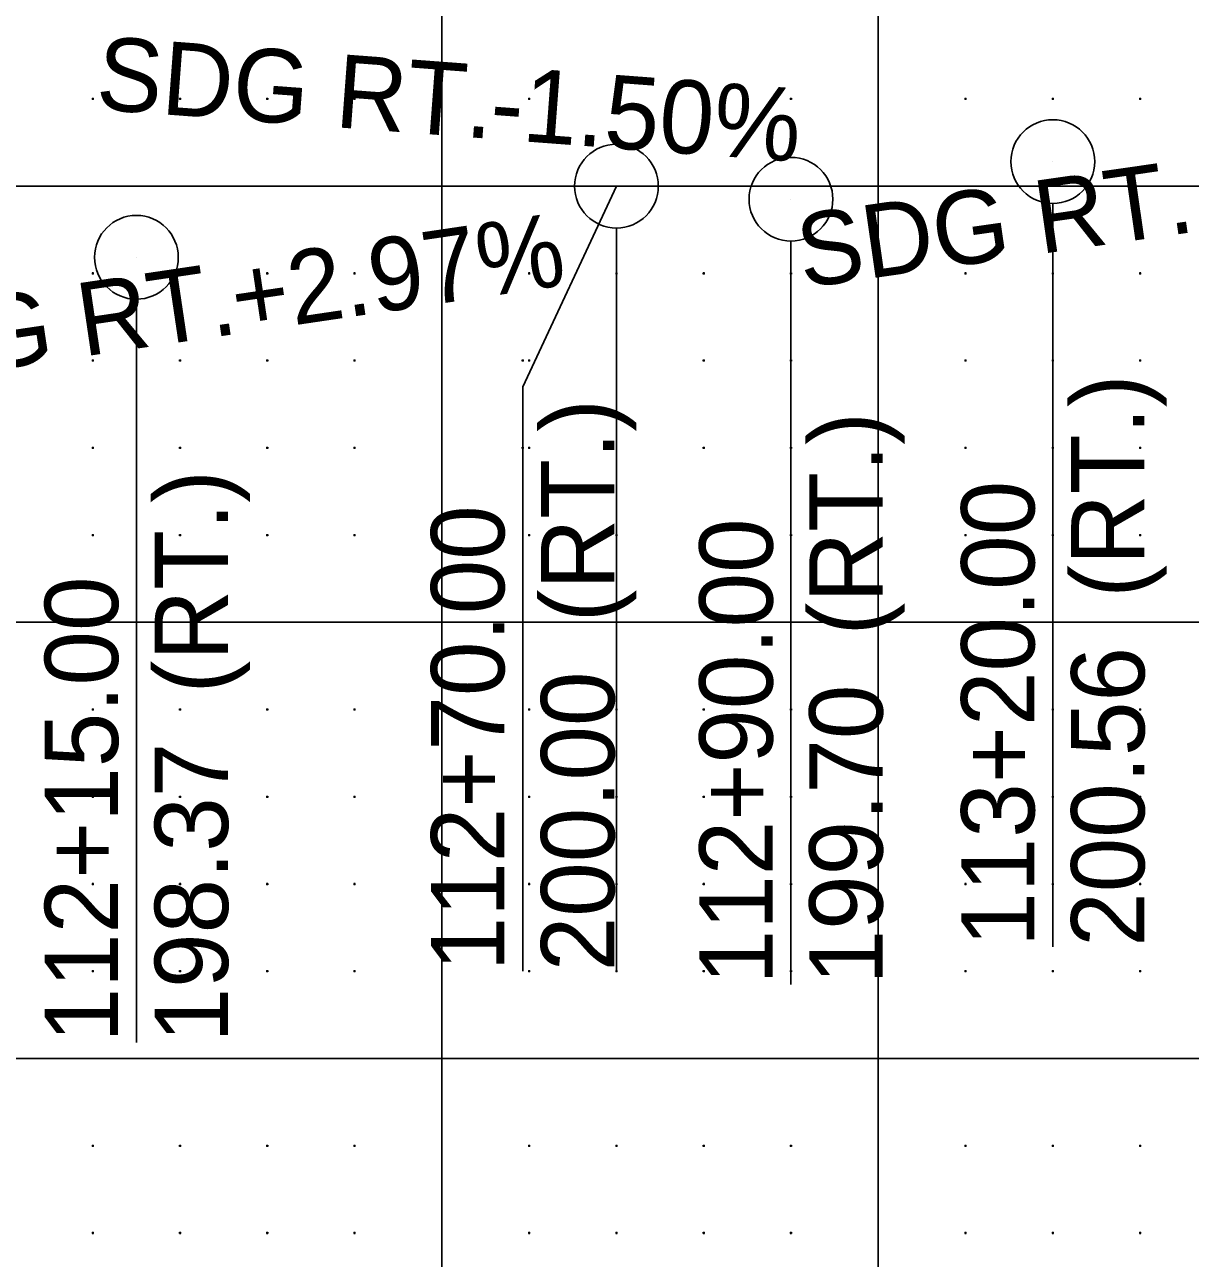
# Model space of a CAD drawing. Extents: x 471 to 2121, y 140 to 650.
# Drawn here: x 1838.3 to 1971.8, y 277.1 to 418.5 of the extents above; entities that cross this region are included whole.
import ezdxf

# ---------------------------------------------------------------- set-up
doc = ezdxf.new("R2010")
doc.units = 0
doc.layers.add('DSN_DRFT_Border Grid', color=7, linetype='Continuous')
doc.layers.add('Triangles', color=7, linetype='Continuous')

msp = doc.modelspace()

# ---------------------------------------------------------------- linework, layer by layer
at = {"layer": 'DSN_DRFT_Border Grid'}
for p, q in [((1886.06, 150), (1886.06, 650)), ((1886.06, 150), (1886.06, 650)), ((1936.06, 150), (1936.06, 650)), ((1936.06, 150), (1936.06, 650)), ((1846.06, 410.12), (1846.06, 409.88)), ((1846.06, 410.12), (1846.06, 409.88)), ((1856.06, 410.12), (1856.06, 409.88)), ((1856.06, 410.12), (1856.06, 409.88)), ((1866.06, 410.12), (1866.06, 409.88)), ((1866.06, 410.12), (1866.06, 409.88)), ((1876.06, 410.12), (1876.06, 409.88)), ((1876.06, 410.12), (1876.06, 409.88)), ((1896.06, 410.12), (1896.06, 409.88)), ((1896.06, 410.12), (1896.06, 409.88)), ((1906.06, 410.12), (1906.06, 409.88)), ((1906.06, 410.12), (1906.06, 409.88)), ((1916.06, 410.12), (1916.06, 409.88)), ((1916.06, 410.12), (1916.06, 409.88)), ((1926.06, 410.12), (1926.06, 409.88)), ((1926.06, 410.12), (1926.06, 409.88)), ((1946.06, 410.12), (1946.06, 409.88)), ((1946.06, 410.12), (1946.06, 409.88)), ((1956.06, 410.12), (1956.06, 409.88)), ((1956.06, 410.12), (1956.06, 409.88)), ((1966.06, 410.12), (1966.06, 409.88)), ((1966.06, 410.12), (1966.06, 409.88)), ((1846.18, 410), (1845.94, 410)), ((1846.18, 410), (1845.94, 410)), ((1856.18, 410), (1855.94, 410)), ((1856.18, 410), (1855.94, 410)), ((1866.18, 410), (1865.94, 410)), ((1866.18, 410), (1865.94, 410)), ((1876.18, 410), (1875.94, 410)), ((1876.18, 410), (1875.94, 410)), ((1896.18, 410), (1895.94, 410)), ((1896.18, 410), (1895.94, 410)), ((1906.18, 410), (1905.94, 410)), ((1906.18, 410), (1905.94, 410)), ((1916.18, 410), (1915.94, 410)), ((1916.18, 410), (1915.94, 410)), ((1926.18, 410), (1925.94, 410)), ((1926.18, 410), (1925.94, 410)), ((1946.18, 410), (1945.94, 410)), ((1946.18, 410), (1945.94, 410)), ((1956.18, 410), (1955.94, 410)), ((1956.18, 410), (1955.94, 410)), ((1966.18, 410), (1965.94, 410)), ((1966.18, 410), (1965.94, 410)), ((521.06, 400), (2071.06, 400)), ((521.06, 400), (2071.06, 400)), ((1846.18, 390), (1845.94, 390)), ((1846.18, 390), (1845.94, 390)), ((1846.06, 390.12), (1846.06, 389.88)), ((1846.06, 390.12), (1846.06, 389.88)), ((1856.18, 390), (1855.94, 390)), ((1856.18, 390), (1855.94, 390)), ((1856.06, 390.12), (1856.06, 389.88)), ((1856.06, 390.12), (1856.06, 389.88)), ((1866.18, 390), (1865.94, 390)), ((1866.18, 390), (1865.94, 390)), ((1866.06, 390.12), (1866.06, 389.88)), ((1866.06, 390.12), (1866.06, 389.88)), ((1876.18, 390), (1875.94, 390)), ((1876.18, 390), (1875.94, 390)), ((1876.06, 390.12), (1876.06, 389.88)), ((1876.06, 390.12), (1876.06, 389.88)), ((1896.18, 390), (1895.94, 390)), ((1896.18, 390), (1895.94, 390)), ((1896.06, 390.12), (1896.06, 389.88)), ((1896.06, 390.12), (1896.06, 389.88)), ((1906.18, 390), (1905.94, 390)), ((1906.18, 390), (1905.94, 390)), ((1906.06, 390.12), (1906.06, 389.88)), ((1906.06, 390.12), (1906.06, 389.88)), ((1916.18, 390), (1915.94, 390)), ((1916.18, 390), (1915.94, 390)), ((1916.06, 390.12), (1916.06, 389.88)), ((1916.06, 390.12), (1916.06, 389.88)), ((1926.18, 390), (1925.94, 390)), ((1926.18, 390), (1925.94, 390)), ((1926.06, 390.12), (1926.06, 389.88)), ((1926.06, 390.12), (1926.06, 389.88)), ((1946.18, 390), (1945.94, 390)), ((1946.18, 390), (1945.94, 390)), ((1946.06, 390.12), (1946.06, 389.88)), ((1946.06, 390.12), (1946.06, 389.88)), ((1956.18, 390), (1955.94, 390)), ((1956.18, 390), (1955.94, 390)), ((1956.06, 390.12), (1956.06, 389.88)), ((1956.06, 390.12), (1956.06, 389.88)), ((1966.18, 390), (1965.94, 390)), ((1966.18, 390), (1965.94, 390)), ((1966.06, 390.12), (1966.06, 389.88)), ((1966.06, 390.12), (1966.06, 389.88)), ((1846.18, 380), (1845.94, 380)), ((1846.18, 380), (1845.94, 380)), ((1846.06, 380.12), (1846.06, 379.88)), ((1846.06, 380.12), (1846.06, 379.88)), ((1856.18, 380), (1855.94, 380)), ((1856.18, 380), (1855.94, 380)), ((1856.06, 380.12), (1856.06, 379.88)), ((1856.06, 380.12), (1856.06, 379.88)), ((1866.18, 380), (1865.94, 380)), ((1866.18, 380), (1865.94, 380)), ((1866.06, 380.12), (1866.06, 379.88)), ((1866.06, 380.12), (1866.06, 379.88)), ((1876.18, 380), (1875.94, 380)), ((1876.18, 380), (1875.94, 380)), ((1876.06, 380.12), (1876.06, 379.88)), ((1876.06, 380.12), (1876.06, 379.88)), ((1895.44, 380), (1895.2, 380)), ((1895.44, 380), (1895.2, 380)), ((1895.32, 380.12), (1895.32, 379.88)), ((1895.32, 380.12), (1895.32, 379.88)), ((1896.18, 380), (1895.94, 380)), ((1896.18, 380), (1895.94, 380)), ((1896.06, 380.12), (1896.06, 379.88)), ((1896.06, 380.12), (1896.06, 379.88)), ((1916.18, 380), (1915.94, 380)), ((1916.18, 380), (1915.94, 380)), ((1916.06, 380.12), (1916.06, 379.88)), ((1916.06, 380.12), (1916.06, 379.88)), ((1926.18, 380), (1925.94, 380)), ((1926.18, 380), (1925.94, 380)), ((1926.06, 380.12), (1926.06, 379.88)), ((1926.06, 380.12), (1926.06, 379.88)), ((1946.18, 380), (1945.94, 380)), ((1946.18, 380), (1945.94, 380)), ((1946.06, 380.12), (1946.06, 379.88)), ((1946.06, 380.12), (1946.06, 379.88)), ((1956.18, 380), (1955.94, 380)), ((1956.18, 380), (1955.94, 380)), ((1956.06, 380.12), (1956.06, 379.88)), ((1956.06, 380.12), (1956.06, 379.88)), ((1966.18, 380), (1965.94, 380)), ((1966.18, 380), (1965.94, 380)), ((1966.06, 380.12), (1966.06, 379.88)), ((1966.06, 380.12), (1966.06, 379.88)), ((1846.18, 370), (1845.94, 370)), ((1846.18, 370), (1845.94, 370)), ((1846.06, 370.12), (1846.06, 369.88)), ((1846.06, 370.12), (1846.06, 369.88)), ((1856.18, 370), (1855.94, 370)), ((1856.18, 370), (1855.94, 370)), ((1856.06, 370.12), (1856.06, 369.88)), ((1856.06, 370.12), (1856.06, 369.88)), ((1866.18, 370), (1865.94, 370)), ((1866.18, 370), (1865.94, 370)), ((1866.06, 370.12), (1866.06, 369.88)), ((1866.06, 370.12), (1866.06, 369.88)), ((1876.18, 370), (1875.94, 370)), ((1876.18, 370), (1875.94, 370)), ((1876.06, 370.12), (1876.06, 369.88)), ((1876.06, 370.12), (1876.06, 369.88)), ((1895.44, 370), (1895.2, 370)), ((1895.44, 370), (1895.2, 370)), ((1895.32, 370.12), (1895.32, 369.88)), ((1895.32, 370.12), (1895.32, 369.88)), ((1896.18, 370), (1895.94, 370)), ((1896.18, 370), (1895.94, 370)), ((1896.06, 370.12), (1896.06, 369.88)), ((1896.06, 370.12), (1896.06, 369.88)), ((1916.18, 370), (1915.94, 370)), ((1916.18, 370), (1915.94, 370)), ((1916.06, 370.12), (1916.06, 369.88)), ((1916.06, 370.12), (1916.06, 369.88)), ((1926.18, 370), (1925.94, 370)), ((1926.18, 370), (1925.94, 370)), ((1926.06, 370.12), (1926.06, 369.88)), ((1926.06, 370.12), (1926.06, 369.88)), ((1946.18, 370), (1945.94, 370)), ((1946.18, 370), (1945.94, 370)), ((1946.06, 370.12), (1946.06, 369.88)), ((1946.06, 370.12), (1946.06, 369.88)), ((1956.18, 370), (1955.94, 370)), ((1956.18, 370), (1955.94, 370)), ((1956.06, 370.12), (1956.06, 369.88)), ((1956.06, 370.12), (1956.06, 369.88)), ((1966.18, 370), (1965.94, 370)), ((1966.18, 370), (1965.94, 370)), ((1966.06, 370.12), (1966.06, 369.88)), ((1966.06, 370.12), (1966.06, 369.88)), ((1846.18, 360), (1845.94, 360)), ((1846.18, 360), (1845.94, 360)), ((1846.06, 360.12), (1846.06, 359.88)), ((1846.06, 360.12), (1846.06, 359.88)), ((1856.18, 360), (1855.94, 360)), ((1856.18, 360), (1855.94, 360)), ((1856.06, 360.12), (1856.06, 359.88)), ((1856.06, 360.12), (1856.06, 359.88)), ((1866.18, 360), (1865.94, 360)), ((1866.18, 360), (1865.94, 360)), ((1866.06, 360.12), (1866.06, 359.88)), ((1866.06, 360.12), (1866.06, 359.88)), ((1876.18, 360), (1875.94, 360)), ((1876.18, 360), (1875.94, 360)), ((1876.06, 360.12), (1876.06, 359.88)), ((1876.06, 360.12), (1876.06, 359.88)), ((1896.18, 360), (1895.94, 360)), ((1896.18, 360), (1895.94, 360)), ((1896.06, 360.12), (1896.06, 359.88)), ((1896.06, 360.12), (1896.06, 359.88)), ((1906.18, 360), (1905.94, 360)), ((1906.18, 360), (1905.94, 360)), ((1906.06, 360.12), (1906.06, 359.88)), ((1906.06, 360.12), (1906.06, 359.88)), ((1916.18, 360), (1915.94, 360)), ((1916.18, 360), (1915.94, 360)), ((1916.06, 360.12), (1916.06, 359.88)), ((1916.06, 360.12), (1916.06, 359.88)), ((1926.18, 360), (1925.94, 360)), ((1926.18, 360), (1925.94, 360)), ((1926.06, 360.12), (1926.06, 359.88)), ((1926.06, 360.12), (1926.06, 359.88)), ((1946.18, 360), (1945.94, 360)), ((1946.18, 360), (1945.94, 360)), ((1946.06, 360.12), (1946.06, 359.88)), ((1946.06, 360.12), (1946.06, 359.88)), ((1956.18, 360), (1955.94, 360)), ((1956.18, 360), (1955.94, 360)), ((1956.06, 360.12), (1956.06, 359.88)), ((1956.06, 360.12), (1956.06, 359.88)), ((1966.18, 360), (1965.94, 360)), ((1966.18, 360), (1965.94, 360)), ((1966.06, 360.12), (1966.06, 359.88)), ((1966.06, 360.12), (1966.06, 359.88)), ((521.06, 350), (2071.06, 350)), ((521.06, 350), (2071.06, 350)), ((1846.18, 340), (1845.94, 340)), ((1846.18, 340), (1845.94, 340)), ((1846.06, 340.12), (1846.06, 339.88)), ((1846.06, 340.12), (1846.06, 339.88)), ((1856.18, 340), (1855.94, 340)), ((1856.18, 340), (1855.94, 340)), ((1856.06, 340.12), (1856.06, 339.88)), ((1856.06, 340.12), (1856.06, 339.88)), ((1866.18, 340), (1865.94, 340)), ((1866.18, 340), (1865.94, 340)), ((1866.06, 340.12), (1866.06, 339.88)), ((1866.06, 340.12), (1866.06, 339.88)), ((1876.18, 340), (1875.94, 340)), ((1876.18, 340), (1875.94, 340)), ((1876.06, 340.12), (1876.06, 339.88)), ((1876.06, 340.12), (1876.06, 339.88)), ((1896.18, 340), (1895.94, 340)), ((1896.18, 340), (1895.94, 340)), ((1896.06, 340.12), (1896.06, 339.88)), ((1896.06, 340.12), (1896.06, 339.88)), ((1906.18, 340), (1905.94, 340)), ((1906.18, 340), (1905.94, 340)), ((1906.06, 340.12), (1906.06, 339.88)), ((1906.06, 340.12), (1906.06, 339.88)), ((1916.18, 340), (1915.94, 340)), ((1916.18, 340), (1915.94, 340)), ((1916.06, 340.12), (1916.06, 339.88)), ((1916.06, 340.12), (1916.06, 339.88)), ((1926.18, 340), (1925.94, 340)), ((1926.18, 340), (1925.94, 340)), ((1926.06, 340.12), (1926.06, 339.88)), ((1926.06, 340.12), (1926.06, 339.88)), ((1946.18, 340), (1945.94, 340)), ((1946.18, 340), (1945.94, 340)), ((1946.06, 340.12), (1946.06, 339.88)), ((1946.06, 340.12), (1946.06, 339.88)), ((1956.18, 340), (1955.94, 340)), ((1956.18, 340), (1955.94, 340)), ((1956.06, 340.12), (1956.06, 339.88)), ((1956.06, 340.12), (1956.06, 339.88)), ((1966.18, 340), (1965.94, 340)), ((1966.18, 340), (1965.94, 340)), ((1966.06, 340.12), (1966.06, 339.88)), ((1966.06, 340.12), (1966.06, 339.88)), ((1846.18, 330), (1845.94, 330)), ((1846.18, 330), (1845.94, 330)), ((1846.06, 330.12), (1846.06, 329.88)), ((1846.06, 330.12), (1846.06, 329.88)), ((1856.18, 330), (1855.94, 330)), ((1856.18, 330), (1855.94, 330)), ((1856.06, 330.12), (1856.06, 329.88)), ((1856.06, 330.12), (1856.06, 329.88)), ((1866.18, 330), (1865.94, 330)), ((1866.18, 330), (1865.94, 330)), ((1866.06, 330.12), (1866.06, 329.88)), ((1866.06, 330.12), (1866.06, 329.88)), ((1876.18, 330), (1875.94, 330)), ((1876.18, 330), (1875.94, 330)), ((1876.06, 330.12), (1876.06, 329.88)), ((1876.06, 330.12), (1876.06, 329.88)), ((1896.18, 330), (1895.94, 330)), ((1896.18, 330), (1895.94, 330)), ((1896.06, 330.12), (1896.06, 329.88)), ((1896.06, 330.12), (1896.06, 329.88)), ((1906.18, 330), (1905.94, 330)), ((1906.18, 330), (1905.94, 330)), ((1906.06, 330.12), (1906.06, 329.88)), ((1906.06, 330.12), (1906.06, 329.88)), ((1916.18, 330), (1915.94, 330)), ((1916.18, 330), (1915.94, 330)), ((1916.06, 330.12), (1916.06, 329.88)), ((1916.06, 330.12), (1916.06, 329.88)), ((1926.18, 330), (1925.94, 330)), ((1926.18, 330), (1925.94, 330)), ((1926.06, 330.12), (1926.06, 329.88)), ((1926.06, 330.12), (1926.06, 329.88)), ((1946.18, 330), (1945.94, 330)), ((1946.18, 330), (1945.94, 330)), ((1946.06, 330.12), (1946.06, 329.88)), ((1946.06, 330.12), (1946.06, 329.88)), ((1956.18, 330), (1955.94, 330)), ((1956.18, 330), (1955.94, 330)), ((1956.06, 330.12), (1956.06, 329.88)), ((1956.06, 330.12), (1956.06, 329.88)), ((1966.18, 330), (1965.94, 330)), ((1966.18, 330), (1965.94, 330)), ((1966.06, 330.12), (1966.06, 329.88)), ((1966.06, 330.12), (1966.06, 329.88)), ((1846.18, 320), (1845.94, 320)), ((1846.18, 320), (1845.94, 320)), ((1846.06, 320.12), (1846.06, 319.88)), ((1846.06, 320.12), (1846.06, 319.88)), ((1856.18, 320), (1855.94, 320)), ((1856.18, 320), (1855.94, 320)), ((1856.06, 320.12), (1856.06, 319.88)), ((1856.06, 320.12), (1856.06, 319.88)), ((1866.18, 320), (1865.94, 320)), ((1866.18, 320), (1865.94, 320)), ((1866.06, 320.12), (1866.06, 319.88)), ((1866.06, 320.12), (1866.06, 319.88)), ((1876.18, 320), (1875.94, 320)), ((1876.18, 320), (1875.94, 320)), ((1876.06, 320.12), (1876.06, 319.88)), ((1876.06, 320.12), (1876.06, 319.88)), ((1896.18, 320), (1895.94, 320)), ((1896.18, 320), (1895.94, 320)), ((1896.06, 320.12), (1896.06, 319.88)), ((1896.06, 320.12), (1896.06, 319.88)), ((1906.18, 320), (1905.94, 320)), ((1906.18, 320), (1905.94, 320)), ((1906.06, 320.12), (1906.06, 319.88)), ((1906.06, 320.12), (1906.06, 319.88)), ((1916.18, 320), (1915.94, 320)), ((1916.18, 320), (1915.94, 320)), ((1916.06, 320.12), (1916.06, 319.88)), ((1916.06, 320.12), (1916.06, 319.88)), ((1926.18, 320), (1925.94, 320)), ((1926.18, 320), (1925.94, 320)), ((1926.06, 320.12), (1926.06, 319.88)), ((1926.06, 320.12), (1926.06, 319.88)), ((1946.18, 320), (1945.94, 320)), ((1946.18, 320), (1945.94, 320)), ((1946.06, 320.12), (1946.06, 319.88)), ((1946.06, 320.12), (1946.06, 319.88)), ((1956.18, 320), (1955.94, 320)), ((1956.18, 320), (1955.94, 320)), ((1956.06, 320.12), (1956.06, 319.88)), ((1956.06, 320.12), (1956.06, 319.88)), ((1966.18, 320), (1965.94, 320)), ((1966.18, 320), (1965.94, 320)), ((1966.06, 320.12), (1966.06, 319.88)), ((1966.06, 320.12), (1966.06, 319.88)), ((1846.18, 310), (1845.94, 310)), ((1846.18, 310), (1845.94, 310)), ((1846.06, 310.12), (1846.06, 309.88)), ((1846.06, 310.12), (1846.06, 309.88)), ((1856.18, 310), (1855.94, 310)), ((1856.18, 310), (1855.94, 310)), ((1856.06, 310.12), (1856.06, 309.88)), ((1856.06, 310.12), (1856.06, 309.88)), ((1866.18, 310), (1865.94, 310)), ((1866.18, 310), (1865.94, 310)), ((1866.06, 310.12), (1866.06, 309.88)), ((1866.06, 310.12), (1866.06, 309.88)), ((1876.18, 310), (1875.94, 310)), ((1876.18, 310), (1875.94, 310)), ((1876.06, 310.12), (1876.06, 309.88)), ((1876.06, 310.12), (1876.06, 309.88)), ((1896.18, 310), (1895.94, 310)), ((1896.18, 310), (1895.94, 310)), ((1896.06, 310.12), (1896.06, 309.88)), ((1896.06, 310.12), (1896.06, 309.88)), ((1906.18, 310), (1905.94, 310)), ((1906.18, 310), (1905.94, 310)), ((1906.06, 310.12), (1906.06, 309.88)), ((1906.06, 310.12), (1906.06, 309.88)), ((1916.18, 310), (1915.94, 310)), ((1916.18, 310), (1915.94, 310)), ((1916.06, 310.12), (1916.06, 309.88)), ((1916.06, 310.12), (1916.06, 309.88)), ((1926.18, 310), (1925.94, 310)), ((1926.18, 310), (1925.94, 310)), ((1926.06, 310.12), (1926.06, 309.88)), ((1926.06, 310.12), (1926.06, 309.88)), ((1946.18, 310), (1945.94, 310)), ((1946.18, 310), (1945.94, 310)), ((1946.06, 310.12), (1946.06, 309.88)), ((1946.06, 310.12), (1946.06, 309.88)), ((1956.18, 310), (1955.94, 310)), ((1956.18, 310), (1955.94, 310)), ((1956.06, 310.12), (1956.06, 309.88)), ((1956.06, 310.12), (1956.06, 309.88)), ((1966.18, 310), (1965.94, 310)), ((1966.18, 310), (1965.94, 310)), ((1966.06, 310.12), (1966.06, 309.88)), ((1966.06, 310.12), (1966.06, 309.88)), ((521.06, 300), (2071.06, 300)), ((521.06, 300), (2071.06, 300)), ((1846.18, 290), (1845.94, 290)), ((1846.18, 290), (1845.94, 290)), ((1846.06, 290.12), (1846.06, 289.88)), ((1846.06, 290.12), (1846.06, 289.88)), ((1856.18, 290), (1855.94, 290)), ((1856.18, 290), (1855.94, 290)), ((1856.06, 290.12), (1856.06, 289.88)), ((1856.06, 290.12), (1856.06, 289.88)), ((1866.18, 290), (1865.94, 290)), ((1866.18, 290), (1865.94, 290)), ((1866.06, 290.12), (1866.06, 289.88)), ((1866.06, 290.12), (1866.06, 289.88)), ((1876.18, 290), (1875.94, 290)), ((1876.18, 290), (1875.94, 290)), ((1876.06, 290.12), (1876.06, 289.88)), ((1876.06, 290.12), (1876.06, 289.88)), ((1896.18, 290), (1895.94, 290)), ((1896.18, 290), (1895.94, 290)), ((1896.06, 290.12), (1896.06, 289.88)), ((1896.06, 290.12), (1896.06, 289.88)), ((1906.18, 290), (1905.94, 290)), ((1906.18, 290), (1905.94, 290)), ((1906.06, 290.12), (1906.06, 289.88)), ((1906.06, 290.12), (1906.06, 289.88)), ((1916.18, 290), (1915.94, 290)), ((1916.18, 290), (1915.94, 290)), ((1916.06, 290.12), (1916.06, 289.88)), ((1916.06, 290.12), (1916.06, 289.88)), ((1926.18, 290), (1925.94, 290)), ((1926.18, 290), (1925.94, 290)), ((1926.06, 290.12), (1926.06, 289.88)), ((1926.06, 290.12), (1926.06, 289.88)), ((1946.18, 290), (1945.94, 290)), ((1946.18, 290), (1945.94, 290)), ((1946.06, 290.12), (1946.06, 289.88)), ((1946.06, 290.12), (1946.06, 289.88)), ((1956.18, 290), (1955.94, 290)), ((1956.18, 290), (1955.94, 290)), ((1956.06, 290.12), (1956.06, 289.88)), ((1956.06, 290.12), (1956.06, 289.88)), ((1966.18, 290), (1965.94, 290)), ((1966.18, 290), (1965.94, 290)), ((1966.06, 290.12), (1966.06, 289.88)), ((1966.06, 290.12), (1966.06, 289.88)), ((1846.06, 280.12), (1846.06, 279.88)), ((1846.06, 280.12), (1846.06, 279.88)), ((1856.06, 280.12), (1856.06, 279.88)), ((1856.06, 280.12), (1856.06, 279.88)), ((1866.06, 280.12), (1866.06, 279.88)), ((1866.06, 280.12), (1866.06, 279.88)), ((1876.06, 280.12), (1876.06, 279.88)), ((1876.06, 280.12), (1876.06, 279.88)), ((1896.06, 280.12), (1896.06, 279.88)), ((1896.06, 280.12), (1896.06, 279.88)), ((1906.06, 280.12), (1906.06, 279.88)), ((1906.06, 280.12), (1906.06, 279.88)), ((1916.06, 280.12), (1916.06, 279.88)), ((1916.06, 280.12), (1916.06, 279.88)), ((1926.06, 280.12), (1926.06, 279.88)), ((1926.06, 280.12), (1926.06, 279.88)), ((1946.06, 280.12), (1946.06, 279.88)), ((1946.06, 280.12), (1946.06, 279.88)), ((1956.06, 280.12), (1956.06, 279.88)), ((1956.06, 280.12), (1956.06, 279.88)), ((1966.06, 280.12), (1966.06, 279.88)), ((1966.06, 280.12), (1966.06, 279.88)), ((1846.18, 280), (1845.94, 280)), ((1846.18, 280), (1845.94, 280)), ((1856.18, 280), (1855.94, 280)), ((1856.18, 280), (1855.94, 280)), ((1866.18, 280), (1865.94, 280)), ((1866.18, 280), (1865.94, 280)), ((1876.18, 280), (1875.94, 280)), ((1876.18, 280), (1875.94, 280)), ((1896.18, 280), (1895.94, 280)), ((1896.18, 280), (1895.94, 280)), ((1906.18, 280), (1905.94, 280)), ((1906.18, 280), (1905.94, 280)), ((1916.18, 280), (1915.94, 280)), ((1916.18, 280), (1915.94, 280)), ((1926.18, 280), (1925.94, 280)), ((1926.18, 280), (1925.94, 280)), ((1946.18, 280), (1945.94, 280)), ((1946.18, 280), (1945.94, 280)), ((1956.18, 280), (1955.94, 280)), ((1956.18, 280), (1955.94, 280)), ((1966.18, 280), (1965.94, 280)), ((1966.18, 280), (1965.94, 280))]:
    msp.add_line(p, q, dxfattribs=at)
at = {"layer": 'Triangles'}
for p, q in [((1956.06, 402.81), (1956.06, 402.81)), ((1895.32, 376.98), (1906.06, 400)), ((1906.06, 400), (1906.06, 400)), ((1926.06, 398.5), (1926.06, 398.5)), ((1956.06, 312.81), (1956.06, 398.01)), ((1906.06, 310), (1906.06, 395.2)), ((1926.06, 308.5), (1926.06, 393.7)), ((1851.06, 391.84), (1851.06, 391.84)), ((1851.06, 301.84), (1851.06, 387.04)), ((1895.32, 310), (1895.32, 376.98))]:
    msp.add_line(p, q, dxfattribs=at)
for centre in [(1956.06, 402.81), (1906.06, 400), (1926.06, 398.5), (1851.06, 391.84)]:
    msp.add_circle(centre, 4.8, dxfattribs=at)

# ---------------------------------------------------------------- texts
for s, rotation, p in [('SDG RT.', 355.7108, (1846.3, 408.82)), ('-1.50%', 355.7108, (1891.41, 405.43)), ('SDG RT.', 8.1849, (1927.43, 388.3)), ('+2.97%', 8.4378, (1862.56, 383.07)), ('SDG RT.', 8.4378, (1817.81, 376.43)), (' (RT.)', 90, (1966.56, 349.71)), (' (RT.)', 90, (1905.82, 346.89)), (' (RT.)', 90, (1936.56, 345.39)), (' (RT.)', 90, (1861.56, 338.74)), ('113+20.00', 90, (1953.96, 312.81)), ('112+70.00', 90, (1893.22, 310)), ('112+90.00', 90, (1923.96, 308.5)), ('112+15.00', 90, (1848.96, 301.84)), ('200.56', 90, (1966.56, 312.81)), ('200.00', 90, (1905.82, 310)), ('199.70', 90, (1936.56, 308.5)), ('198.37', 90, (1861.56, 301.84))]:
    msp.add_text(s, height=8.4, rotation=rotation, dxfattribs=at).set_placement(p)

doc.saveas('drawing.dxf')
